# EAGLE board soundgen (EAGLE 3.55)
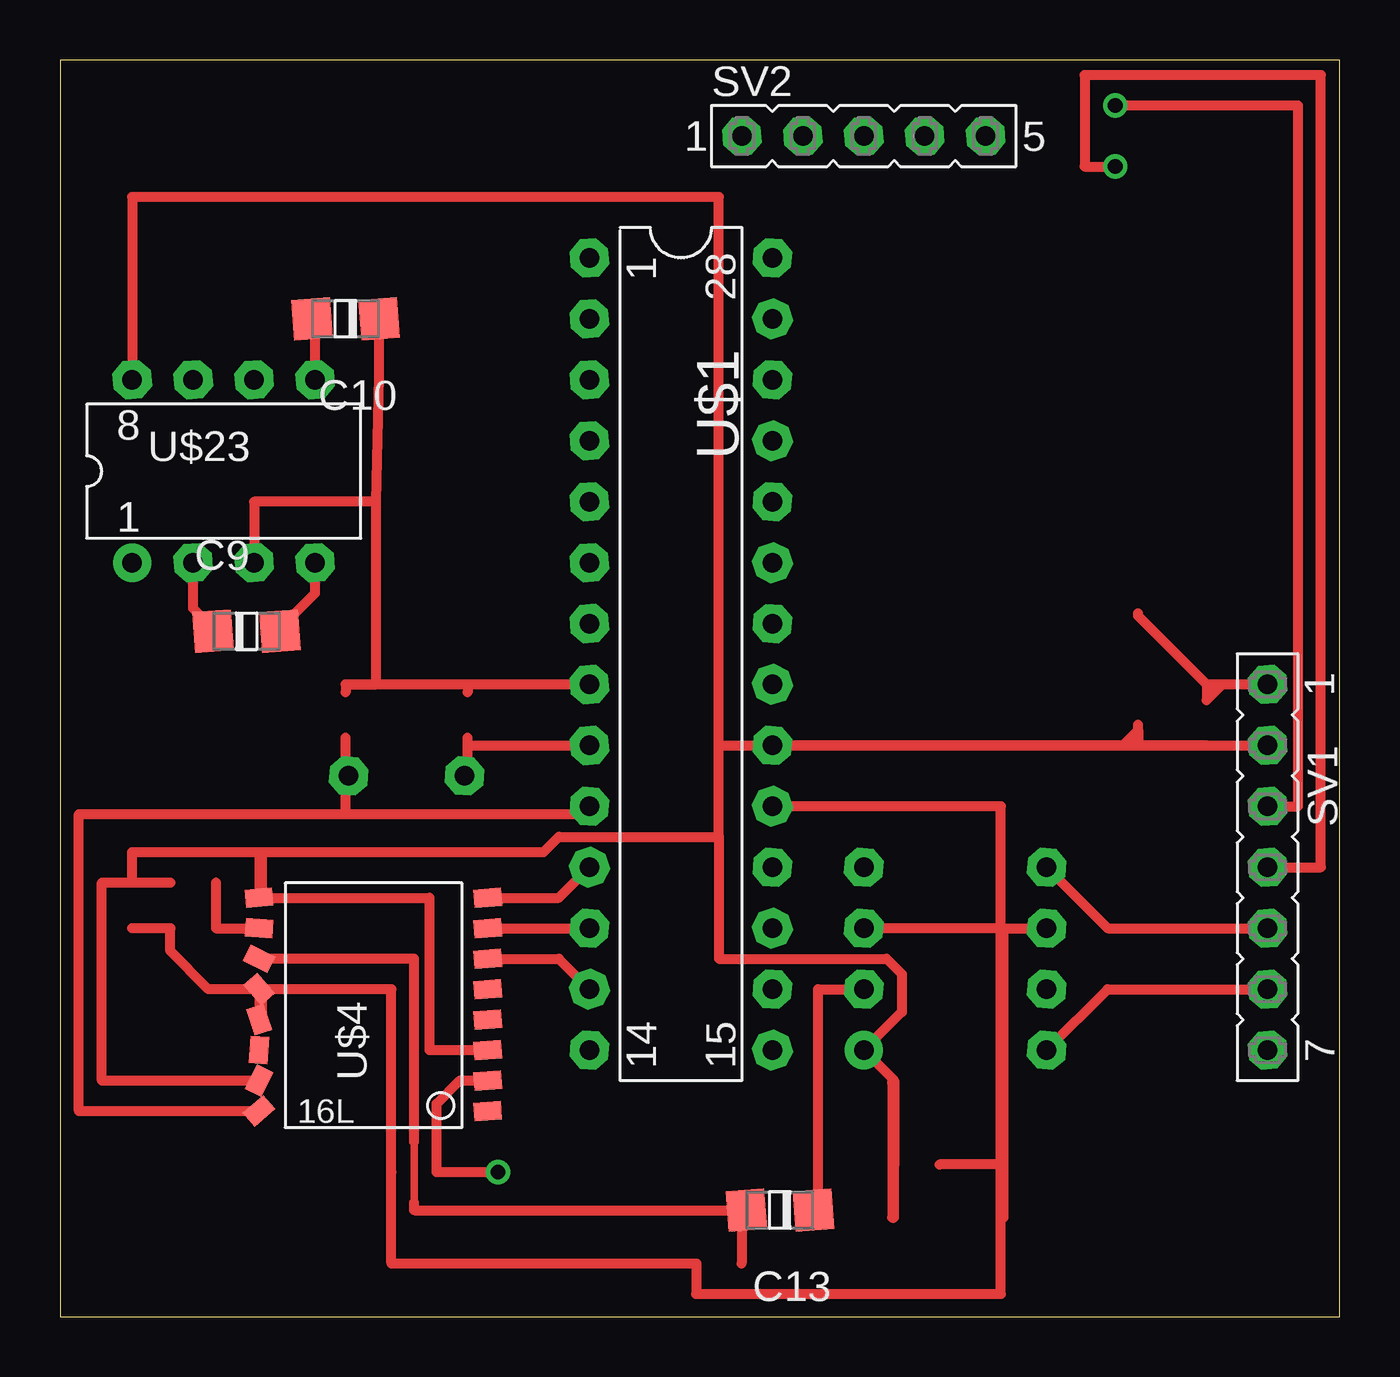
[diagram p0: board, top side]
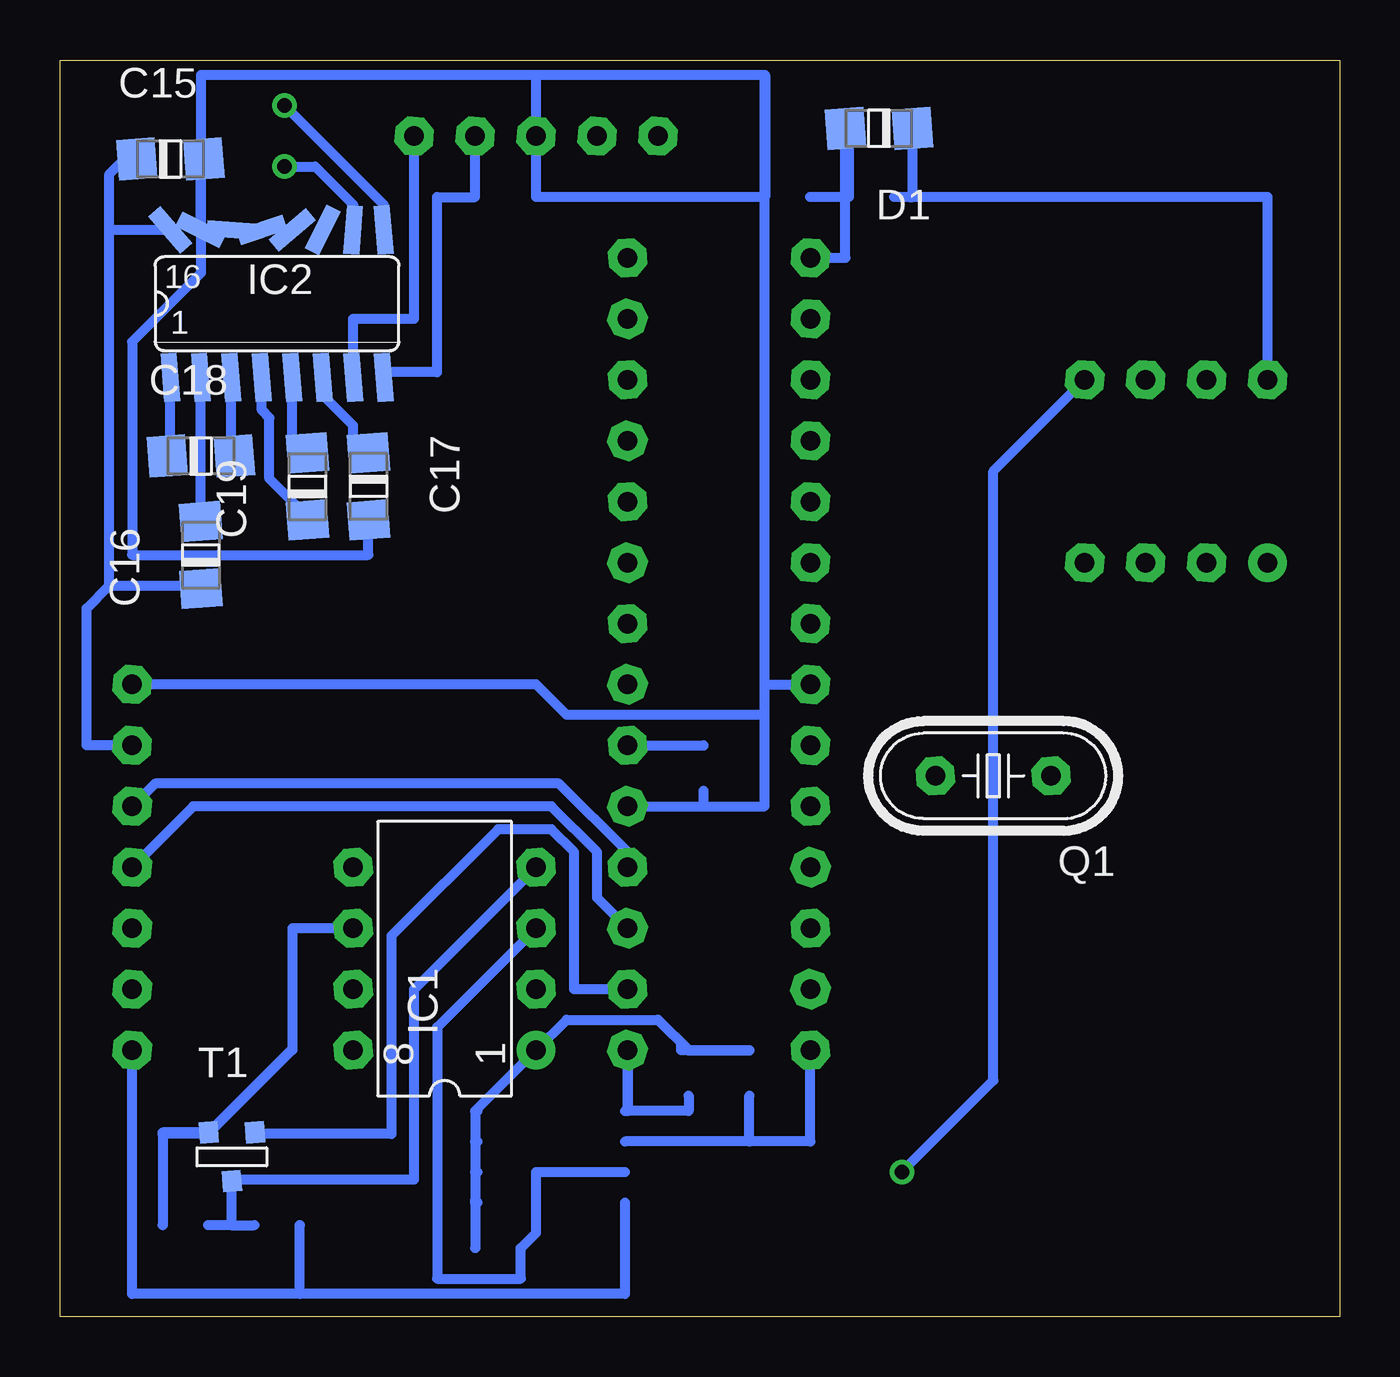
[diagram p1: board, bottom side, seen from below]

Size 53.33 x 52.38 mm. Coordinates in mm from the lower left corner, seen from the top.
Outline: 0,0 53.33,0 53.33,52.38 0,52.38 0,0
Copper layers used: Top, Bottom

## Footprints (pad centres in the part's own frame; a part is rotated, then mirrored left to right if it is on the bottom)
16 = smd 1.6 x 1.702 rotated 4.4:  1.397,0 | smd 1.6 x 1.702 rotated 4.3:  -1.397,0
L8 = drill 0.813 pad 1.6 round:  -3.81,-3.81 | drill 0.813 pad 1.6 octagon:  -1.27,-3.81;  1.27,-3.81;  3.81,-3.81;  3.81,3.81;  1.27,3.81;  -1.27,3.81;  -3.81,3.81
16' = smd 0.66 x 2.032 rotated 4.3:  -4.445,-3.073;  3.175,3.073 | smd 0.66 x 2.032 rotated 139.3:  -4.445,3.073 | smd 0.66 x 2.032 rotated 4.4:  -3.175,-3.073 | smd 0.66 x 2.032 rotated 4.5:  -1.905,-3.073 | smd 0.66 x 2.032 rotated 116.8:  -3.175,3.073 | smd 0.66 x 2.032 rotated 94.3:  -1.905,3.073 | smd 0.66 x 2.032 rotated 4.6:  -0.635,-3.073 | smd 0.66 x 2.032 rotated 71.8:  -0.635,3.073 | smd 0.66 x 2.032 rotated 4.7:  0.635,-3.073;  1.905,-3.073 | smd 0.66 x 2.032 rotated 49.3:  0.635,3.073 | smd 0.66 x 2.032 rotated 4.8:  3.175,-3.073 | smd 0.66 x 2.032 rotated 26.8:  1.905,3.073 | smd 0.66 x 2.032 rotated 4.9:  4.445,-3.073 | smd 0.66 x 2.032 rotated 5:  4.445,3.073
49U-V = drill 0.813 pad 1.6 octagon:  -2.413,0;  2.413,0
07 = drill 0.813 pad 1.6 octagon:  -7.62,0;  -5.08,0;  -2.54,0;  0,0;  2.54,0;  5.08,0;  7.62,0
05-1 = drill 0.813 pad 1.6 octagon:  -5.08,0;  -2.54,0;  0,0;  2.54,0;  5.08,0
T23 = smd 0.787 x 0.889 rotated 4.4:  0.991,1.016 | smd 0.787 x 0.889 rotated 4.3:  -0.94,1.016 | smd 0.787 x 0.889 rotated 4.5:  0.025,-1.016
L28-3 = drill 0.813 pad 1.6 octagon:  -16.51,-3.81;  -13.97,-3.81;  -11.43,-3.81;  -8.89,-3.81;  -6.35,-3.81;  -3.81,-3.81;  -1.27,-3.81;  1.27,-3.81;  3.81,-3.81;  6.35,-3.81;  8.89,-3.81;  11.43,-3.81;  13.97,-3.81;  16.51,-3.81;  16.51,3.81;  13.97,3.81;  11.43,3.81;  8.89,3.81;  6.35,3.81;  3.81,3.81;  1.27,3.81;  -1.27,3.81;  -3.81,3.81;  -6.35,3.81;  -8.89,3.81;  -11.43,3.81;  -13.97,3.81;  -16.51,3.81
16L = smd 0.762 x 1.143 rotated 4.3:  -5.08,-4.648;  2.54,4.877 | smd 0.762 x 1.143 rotated 4.4:  -3.81,-4.648 | smd 0.762 x 1.143 rotated 4.5:  -2.54,-4.648 | smd 0.762 x 1.143 rotated 4.6:  -1.27,-4.648 | smd 0.762 x 1.143 rotated 4.7:  0,-4.648;  1.27,-4.648 | smd 0.762 x 1.143 rotated 4.8:  2.54,-4.648 | smd 0.762 x 1.143 rotated 4.9:  3.81,-4.648 | smd 0.762 x 1.143 rotated 5:  3.81,4.877 | smd 0.762 x 1.143 rotated 26.8:  1.27,4.877 | smd 0.762 x 1.143 rotated 49.3:  0,4.877 | smd 0.762 x 1.143 rotated 71.8:  -1.27,4.877 | smd 0.762 x 1.143 rotated 94.3:  -2.54,4.877 | smd 0.762 x 1.143 rotated 116.8:  -3.81,4.877 | smd 0.762 x 1.143 rotated 139.3:  -5.08,4.877
L08 = drill 0.813 pad 1.6 round:  -3.81,-3.81 | drill 0.813 pad 1.6 octagon:  -1.27,-3.81;  1.27,-3.81;  3.81,-3.81;  3.81,3.81;  1.27,3.81;  -1.27,3.81;  -3.81,3.81

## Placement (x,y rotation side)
C1  100u  [32]  44.92,26.98 90 top
C2  100n  [05]  47.78,24.76 90 top
C3  100n  [05]  26.5,22.86 270 bottom
C4  100n  [05]  3.01,17.14 270 top
C5  100n  [05]  23.01,46.67 180 bottom
C6  22p  [05]  11.9,25.08 90 top
C7  22p  [05]  16.98,25.08 90 top
C8  100n  [05]  14.76,6.03 0 top
C9  10u  [16]  7.77,28.57 0 top
C10  10u  [16]  11.9,41.59 180 top
C11  100u  [32]  36.98,4.12 0 top
C12  100n  [05]  35.71,6.34 0 top
C13  470n  [16]  30,4.44 180 top
C14  100n  [05]  35.08,2.85 0 bottom
C15  100n  [16]  48.73,48.25 0 bottom
C16  100n  [16]  47.46,31.75 90 bottom
C17  100n  [16]  40.47,34.6 270 bottom
C18  100n  [16]  47.46,35.87 0 bottom
C19  100n  [16]  43.02,34.6 90 bottom
D1  DIODE  [16]  19.2,49.52 180 bottom
DAC3  MAX517BCSA  [08]  32.86,6.66 90 bottom
IC1  TDA7052A/A  [L8]  37.3,14.92 90 bottom
IC2  MAX232CSE  [16']  44.28,42.22 0 bottom
Q1  10MHz  [49U-V]  14.44,22.54 180 bottom
R1  10k  [05]  19.52,46.67 0 bottom
R2  10k  [05]  5.55,16.19 180 top
R3  10k  [05]  5.55,18.09 0 top
R4  34k  [05]  44.28,3.8 0 bottom
R5  16k  [05]  48.09,3.8 0 bottom
R6  5k  [05]  27.46,2.22 0 top
R7  10k  [05]  24.6,10.15 90 bottom
R8  10k  [05]  27.14,10.15 270 bottom
SV1  FE07-1  [07]  50.32,18.73 270 top
SV2  FE05-1  [05-1]  33.49,49.21 0 top
T1  DTC144EKA  [T23]  46.19,6.66 0 bottom
U$1  16C73/6  [L28-3]  25.87,27.62 270 top
U$4  ML2036IS  [16L]  13.17,13.65 90 top
U$23  LTC1046  [L08]  6.82,35.24 0 top

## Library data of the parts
C1-C19 D1 R1-R8 = SMD
DAC3 IC2 = MAXIM
IC1 = Philips
Q1 = QUARTZ
SV1 SV2 = CON-LSTA
T1 = Transist
U$1 = PIC
U$4 = MicroLin
U$23 = LINEAR

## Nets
-5V: C8. C10. U$4. U$23.
DGND: C1. C2. C3. C4. C5. C6. C7. C8. C10. C11. C12. C14. C15. C17. DAC3. IC1. IC2. R2. R5. R6. SV1. SV2. T1. U$1. U$4. U$23.
N$1: C7. Q1. U$1.
N$2: C6. Q1. U$1. U$4.
N$3: C9. U$23.
N$4: U$1. U$4.
N$7: U$1. U$4.
N$8: U$1. U$4.
N$9: R2. R3. U$4.
N$10: C9. U$23.
N$11: C13. R6. U$4.
N$12: IC1. R4. R5. T1.
N$13: DAC3. R8. U$1.
N$14: C5. D1. R1. U$1.
N$15: DAC3. R4. SV1.
N$16: C13. IC1.
N$17: IC1. SV1.
N$18: IC1. SV1.
N$19: DAC3. R7. U$1.
N$20: T1. U$1.
N$21: IC2. SV1. U$1.
N$22: IC2. SV1. U$1.
N$23: C18. IC2.
N$24: C18. IC2.
N$25: C19. IC2.
N$26: C19. IC2.
N$27: C17. IC2.
N$28: C16. IC2.
N$29: IC2. SV2.
N$86: IC2. SV2.
VDD: C1. C2. C3. C4. C11. C12. C14. C15. C16. D1. DAC3. IC1. IC2. R1. R3. R7. R8. SV1. U$1. U$4. U$23.

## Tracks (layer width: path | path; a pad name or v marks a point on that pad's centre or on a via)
-5V  (via drill 0.61 pad 1.02)
  Top 0.406: 17.93,9.84 17.82,9.84 16.66,9.84 15.7,8.87 15.7,6.03 v18.25,6.03 | 10.5,41.59 10.63,41.59 10.63,39.05
  Bottom 0.406: v18.25,6.03 14.44,9.84 14.44,35.24 10.63,39.05
DGND
  Top 0.406: 16.98,26.35 22.06,26.35 11.9,26.35 | 16.98,26.35 16.98,26.02 | 16.98,26.35 13.17,26.35 | 4.6,16.17 4.61,16.19 | 4.6,16.17 4.6,15.23 6.18,13.65 8.29,13.65 | 8.29,13.65 8.41,13.53 8.41,12.38 | 3.01,16.2 3.02,16.19 4.6,16.19 4.6,16.17 | 8.41,12.38 8.29,12.38 8.29,13.53 8.41,13.65 | 8.41,13.65 8.41,12.38 | 13.8,13.65 8.41,13.65 | 13.8,6.03 13.82,6.03 | 8.41,13.65 8.29,13.65 | C10. 13.3,39.17 13.17,33.97 | 8.09,31.11 8.09,31.43 8.09,33.97 13.17,33.97 | 36.65,6.34 39.2,6.34 39.2,4.12 | 13.17,26.35 13.17,33.97 | 11.9,26.35 13.17,26.35 | 13.8,13.65 8.29,13.65 | 13.8,6.03 13.8,13.65 | 13.8,6.03 13.8,2.22 26.52,2.22 | 11.9,26.35 11.9,26.02 | 26.52,2.22 26.52,0.96 26.5,0.95 | 26.52,2.22 26.5,2.22 26.5,0.95 | 26.5,0.95 39.2,0.95 39.2,4.12 | 39.2,4.12 39.32,4.12 | 39.2,4.12 39.2,16.19 | 39.32,4.12 39.32,16.19 39.2,16.19 | 39.32,4.12 39.2,4.24 39.2,16.19 | 39.2,16.19 33.49,16.19 | 47.78,26.35 47.78,25.7 48.42,26.35 50.32,26.35 47.78,26.35 | 44.92,29.32 44.92,29.21 47.78,26.35 | 39.2,16.19 39.2,21.27 | 39.2,16.19 41.11,16.19 | 39.2,21.27 29.68,21.27 | 39.2,4.12 39.2,21.27
  Bottom 0.406: 47.33,48.25 47.46,48.25 47.46,45.4 | 40.47,33.21 40.47,31.74 50.32,31.74 50.32,40.64 47.46,43.49 47.46,45.3 47.46,45.4 | 47.46,48.57 47.46,45.4 | 47.46,48.89 47.46,48.57 | 47.33,48.25 47.33,48.89 47.46,48.89 | 47.46,51.75 47.46,48.89 | 47.33,48.25 47.33,48.57 47.46,48.57 | 47.46,51.75 47.46,48.57 | 47.46,51.75 47.46,45.4 | 33.49,51.75 47.46,51.75 | 29.78,6.03 33.49,6.03 33.49,3.49 34.12,2.85 | 49.05,7.62 49.05,7.68 47.13,7.68 43.65,11.16 43.65,16.19 | 23.95,46.67 23.95,51.75 23.96,51.75 | 26.5,21.92 26.5,21.27 29.68,21.27 23.96,21.27 23.96,25.08 | 23.96,26.35 22.06,26.35 | 33.49,51.75 33.49,49.21 33.49,46.67 23.96,46.67 | 23.96,51.75 33.49,51.75 | 23.96,46.67 23.96,51.75 | 23.96,26.35 23.96,46.67 | 23.96,25.08 23.96,26.35 | 34.12,2.85 34.14,2.85 | 41.11,16.19 43.65,16.19 | 43.65,16.19 43.65,11.11 47.14,7.62 49.05,7.62 | 49.03,3.8 49.05,3.8 49.05,7.62 | 23.96,25.08 23.96,46.67 | 50.32,26.35 33.49,26.35 32.22,25.08 23.96,25.08 | 34.12,2.85 34.12,1.58 37.62,1.58 37.62,12.06 33.49,16.19
N$1
  Top 0.406: Q1. 16.98,22.54 16.98,23.81 | 16.98,23.81 16.98,24.14 | 16.98,23.81 22.06,23.81
N$2
  Top 0.406: 12.22,22.54 12.03,22.54 11.9,22.54 | 11.9,22.54 11.9,24.14 | 22.06,21.27 22.06,20.95 11.9,20.95 | U$4. 0.79,8.57 0.79,20.95 11.9,20.95 | 11.9,20.95 11.9,22.54
N$3
  Top 0.406: C9. 6.5,28.57 5.55,29.52 5.55,31.43
N$4
  Top 0.406: 17.82,17.46 20.79,17.46 22.06,18.73
N$7
  Top 0.406: 17.82,16.19 22.06,16.19
N$8
  Top 0.406: 17.82,14.92 20.79,14.92 22.06,13.65
N$9
  Top 0.406: 8.29,16.19 6.49,16.19 6.5,16.19 6.5,18.09 6.49,18.09
N$10
  Top 0.406: 9.17,28.57 9.04,28.57 10.63,30.16 10.63,31.43
N$11
  Top 0.305: 14.76,4.76 14.76,7.3
  Top 0.406: 8.29,14.92 14.76,14.92 14.76,7.3 | 14.76,4.76 14.76,4.44 28.41,4.44 | 28.41,4.44 28.6,4.44 | 28.4,2.22 28.4,4.43 28.41,4.44
N$12
  Bottom 0.406: 46.19,5.71 46.19,5.65 | 46.19,5.65 T1. | 46.19,3.8 45.22,3.8 | 46.19,5.65 46.19,3.8 | 33.49,18.73 38.57,13.65 38.57,5.71 46.19,5.71 | 46.19,5.71 46.19,3.8 | 47.16,3.8 47.14,3.8 46.19,3.8
N$13
  Bottom 0.406: 29.78,8.57 29.68,8.67 29.68,11.11 29.68,8.57 27.14,8.57 27.14,9.22
N$14
  Bottom 0.406: 22.06,44.13 20.6,44.13 20.6,49.53 20.46,49.53 20.46,46.67 22.07,46.67
N$15
  Bottom 0.406: 29.78,4.76 29.78,0.95 43.33,0.95 | SV1. 50.32,0.95 43.33,0.95 | 43.34,3.8 43.33,3.8 43.33,0.95
N$16
  Top 0.406: C13. 31.58,4.44 31.58,13.65 33.49,13.65
N$17
  Top 0.406: IC1. 43.65,13.65 50.32,13.65
N$18
  Top 0.406: 41.11,18.73 43.65,16.19 50.32,16.19
N$19
  Bottom 0.406: 22.06,11.11 22.06,7.3 24.6,7.3 | 24.6,7.3 29.78,7.3 | 24.6,7.3 24.6,9.22
N$20
  Bottom 0.406: 29.68,13.65 31.9,13.65 31.9,19.36 32.86,20.31 35.08,20.31 39.52,15.87 39.52,7.62 45.2,7.62 | 45.2,7.62 45.24,7.62 | 45.2,7.62 45.2,7.68
N$21  (via drill 0.61 pad 1.02)
  Top 0.406: 50.32,21.27 51.59,21.27 51.59,50.48 v43.97,50.48
  Bottom 0.406: 50.32,21.27 49.37,22.22 32.54,22.22 29.68,19.36 29.68,18.73 | IC2. 39.84,46.35 v43.97,50.48
N$22  (via drill 0.61 pad 1.02)
  Top 0.406: 50.32,18.73 52.54,18.73 52.54,51.75 42.7,51.75 42.7,47.94 v43.97,47.94
  Bottom 0.406: 50.32,18.73 47.78,21.27 32.86,21.27 30.95,19.36 30.95,17.46 29.68,16.19 | 41.11,45.3 41.11,46.35 42.7,47.94 v43.97,47.94
N$23
  Bottom 0.406: C18. 48.73,35.87 48.73,39.15
N$24
  Bottom 0.406: 46.06,35.87 46.19,35.87 46.19,39.15
N$25
  Bottom 0.406: 44.92,39.15 44.92,37.78 44.6,37.46 44.6,34.92 43.02,33.33 C19.
N$26
  Bottom 0.406: 43.02,36 43.65,36 43.65,39.15
N$27
  Bottom 0.406: C17. 41.11,36 41.11,37.14 42.38,38.41 42.38,39.15
N$28
  Bottom 0.406: 47.46,32.7 47.46,33.14 47.46,39.15
N$29
  Bottom 0.406: SV2. 38.57,41.59 41.11,41.59 41.11,39.15 41.11,39.05
N$86
  Bottom 0.406: 39.84,39.15 39.84,39.36 37.62,39.36 37.62,46.67 36.03,46.67 36.03,49.21
VDD
  Top 0.406: 15.39,11.11 17.82,11.11 | 8.41,17.46 8.29,17.46 8.29,19.25 8.41,19.36 | 3.01,18.09 3.01,18.08 | 3.01,18.09 4.61,18.09 | 3.01,18.09 3.01,19.36 8.41,19.36 | 3.01,18.09 1.74,18.09 1.74,9.84 8.29,9.84 8.41,9.84 | 44.92,24.44 44.92,23.81 47.78,23.81 | 29.68,23.81 29.69,23.82 47.78,23.82 47.78,23.81 | 34.76,9.84 34.76,6.34 | 34.77,6.34 34.76,6.33 34.76,4.12 34.67,4.12 34.67,9.75 34.76,9.84 | 44.28,23.81 29.68,23.81 | 44.28,23.81 47.78,23.81 | U$23. 3.01,46.67 27.46,46.67 27.46,23.81 | 47.78,23.81 50.32,23.81 44.28,23.81 | 34.76,9.84 33.49,11.11 35.08,12.7 35.08,14.28 34.44,14.92 27.46,14.92 27.46,20 | 27.46,20 27.46,23.81 | 44.92,24.44 44.92,24.67 | 27.46,23.81 44.28,23.81 | 44.28,23.81 44.92,24.44 | 27.46,23.81 29.68,23.81 | 27.46,20 20.79,20 20.15,19.36 8.41,19.36 | 8.41,19.36 8.41,17.46 | 8.41,17.46 15.39,17.46 15.39,11.11 | 17.82,11.11 17.93,11.11 | 15.39,11.11 17.82,11.11
  Bottom 0.406: 50,48.25 C15. 50.64,48.25 51.27,47.62 51.27,45.4 | 17.93,46.67 17.81,46.67 D1. 17.81,46.79 17.93,46.67 | 36.03,4.76 35.93,4.76 36.03,4.86 36.03,8.57 | 36.03,6.03 36.03,4.76 | 36.03,6.03 35.93,6.03 | 36.03,7.3 36.03,6.03 | 36.03,7.3 35.93,7.3 | 36.03,8.57 35.93,8.57 | 36.03,8.57 36.03,7.3 | 36.02,2.85 36.03,2.85 36.03,4.76 | 26.5,23.79 26.5,23.81 29.68,23.81 | 17.93,46.67 18.58,46.67 | 17.93,46.67 3.01,46.67 U$23. | C16. 47.46,30.47 51.27,30.47 | 32.22,12.38 28.42,12.38 27.14,11.09 24.6,11.09 24.6,11.11 | 48.73,45.3 51.17,45.3 51.27,45.4 | 51.27,30.47 51.27,45.4 | 51.27,30.47 52.22,29.52 52.22,23.81 50.32,23.81 | 36.03,8.57 33.49,11.11 32.22,12.38 | 28.41,12.38 27.14,11.11 24.6,11.11 | 24.6,11.11 27.46,11.11 27.46,11.42 28.41,12.38 | 32.22,12.38 28.41,12.38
